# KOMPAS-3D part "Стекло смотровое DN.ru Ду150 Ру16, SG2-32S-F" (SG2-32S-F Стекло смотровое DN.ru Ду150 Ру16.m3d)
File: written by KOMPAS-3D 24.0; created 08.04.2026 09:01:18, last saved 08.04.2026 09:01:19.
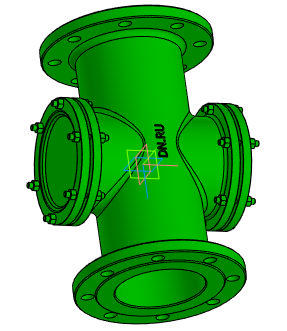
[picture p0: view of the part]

Document properties: Автор: Main; Полное имя файла: D:\DN.ru Аутсерс\Стекло смотровое DN.ru\SG2-32S-F Стекло смотровое DN.ru Ду150 Ру16\SG2-32S-F Стекло смотровое DN.ru Ду150 Ру16.m3d

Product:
- Body: Тело 1  | qty 1
    Масса: 46.781742
- Part/product: Стекло смотровое DN.ru Ду150 Ру16  | designation SG2-32S-F
    Масса: 42
    Раздел спецификации: Прочие изделия
    Примечание: D500-00113

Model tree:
1. Операция без истории:1

Expressions: SG2-32S-F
